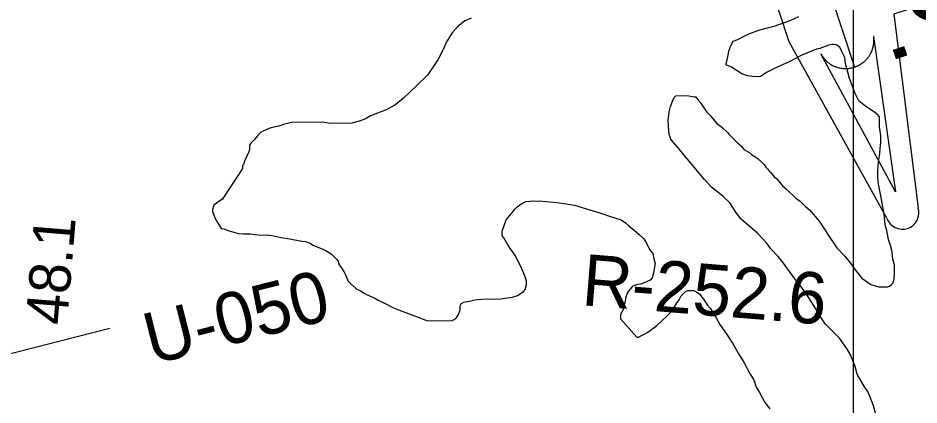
# Model space of a CAD drawing. Extents: x 3263578 to 3301413, y 764927 to 798602.
# Drawn here: x 3295210 to 3296664, y 777411 to 778036 of the extents above; entities that cross this region are included whole.
import ezdxf

# ---------------------------------------------------------------- set-up
doc = ezdxf.new("R2010")
doc.units = 0
for name, color, linetype in [('V-GRID-MAJR', 7, 'Continuous'), ('V-RIVR-RANG', 7, 'Continuous'), ('V-RIVR-RANG-IDEN', 7, 'Continuous'), ('V-SITE-VEGE', 7, 'Continuous'), ('V-TOPO-WATR-IDEN', 7, 'Continuous')]:
    doc.layers.add(name, color=color, linetype=linetype)

msp = doc.modelspace()

# ---------------------------------------------------------------- linework, layer by layer
at = {"layer": 'V-GRID-MAJR'}
msp.add_spline([(3296559.4, 775831.5), (3296556.8, 781892.5), (3296554.1, 787954.5), (3296551.5, 794016.6), (3296551.5, 794017.6)], degree=3, dxfattribs=at)
at = {"layer": 'V-RIVR-RANG'}
msp.add_line((3295358.3, 777534.4), (3294157.4, 777225.6), dxfattribs=at)
at = {"layer": 'V-SITE-VEGE'}
for p, q in [((3295930.9, 778031.6), (3295919.1, 778021.9)), ((3295941.1, 778036), (3295930.9, 778031.6)), ((3296430.5, 778023.1), (3296456, 778032.1)), ((3296456, 778032.1), (3296470.4, 778038.4)), ((3295910.7, 778012.3), (3295901.6, 777997.6)), ((3295919.1, 778021.9), (3295910.7, 778012.3)), ((3296389.6, 778010.3), (3296407.5, 778016.7)), ((3296407.5, 778016.7), (3296417.7, 778019.4)), ((3296417.7, 778019.4), (3296430.5, 778023.1)), ((3295901.6, 777997.6), (3295896.6, 777986.4)), ((3296360.8, 777992.6), (3296364.1, 777998.7)), ((3296364.1, 777998.7), (3296371.8, 778001.4)), ((3296371.8, 778001.4), (3296378.6, 778005)), ((3296378.6, 778005), (3296389.6, 778010.3)), ((3295896.6, 777986.4), (3295887.6, 777968.2)), ((3296354.4, 777968.5), (3296357.6, 777984)), ((3296357.6, 777984), (3296360.8, 777992.6)), ((3296498.9, 777985.8), (3296484.4, 777979.6)), ((3296504, 777986.8), (3296498.9, 777985.8)), ((3296518.4, 777992.2), (3296504, 777986.8)), ((3296523.6, 777993.2), (3296518.4, 777992.2)), ((3296527, 777993.2), (3296523.6, 777993.2)), ((3296530.4, 777992.4), (3296527, 777993.2)), ((3296536.5, 777989.1), (3296530.4, 777992.4)), ((3296539.2, 777983.2), (3296536.5, 777989.1)), ((3296544.5, 777972.1), (3296539.2, 777983.2)), ((3295887.6, 777968.2), (3295870.9, 777943.9)), ((3296352.8, 777962.5), (3296354.4, 777968.5)), ((3296475.1, 777976), (3296454.7, 777965.3)), ((3296484.4, 777979.6), (3296475.1, 777976)), ((3296545.6, 777962.7), (3296544.5, 777972.1)), ((3296352.9, 777959.9), (3296352.8, 777962.5)), ((3296355.5, 777959.1), (3296352.9, 777959.9)), ((3296361.5, 777956.7), (3296355.5, 777959.1)), ((3296378, 777945.8), (3296361.5, 777956.7)), ((3296430.9, 777954.6), (3296419.1, 777948.3)), ((3296440.3, 777959), (3296430.9, 777954.6)), ((3296454.7, 777965.3), (3296440.3, 777959)), ((3296549.3, 777948.3), (3296545.6, 777962.7)), ((3295870.9, 777943.9), (3295853.2, 777926.4)), ((3296387.5, 777942.6), (3296378, 777945.8)), ((3296400.3, 777941.1), (3296387.5, 777942.6)), ((3296408.1, 777941.3), (3296400.3, 777941.1)), ((3296419.1, 777948.3), (3296408.1, 777941.3)), ((3296552, 777938), (3296549.3, 777948.3)), ((3296561.1, 777914.2), (3296552, 777938)), ((3295853.2, 777926.4), (3295832.2, 777906.3)), ((3296269.1, 777907.8), (3296271.6, 777910.4)), ((3296271.6, 777910.4), (3296289.6, 777910.8)), ((3296289.6, 777910.8), (3296301.6, 777908.4)), ((3296567.3, 777902.3), (3296561.1, 777914.2)), ((3295817.9, 777894.9), (3295804.3, 777887.8)), ((3295832.2, 777906.3), (3295817.9, 777894.9)), ((3296263.3, 777893.1), (3296266.6, 777902.6)), ((3296266.6, 777902.6), (3296269.1, 777907.8)), ((3296301.6, 777908.4), (3296304.2, 777908.5)), ((3296304.2, 777908.5), (3296307.7, 777903.4)), ((3296307.7, 777903.4), (3296312.1, 777898.3)), ((3296312.1, 777898.3), (3296314.7, 777894.1)), ((3296569.9, 777899.8), (3296567.3, 777902.3)), ((3296578.6, 777893.1), (3296569.9, 777899.8)), ((3295804.3, 777887.8), (3295778.8, 777877.9)), ((3296259.5, 777870.8), (3296260.9, 777884.5)), ((3296260.9, 777884.5), (3296263.3, 777893.1)), ((3296314.7, 777894.1), (3296321.8, 777884)), ((3296321.8, 777884), (3296327.9, 777878.1)), ((3296587.3, 777887.3), (3296578.6, 777893.1)), ((3296596.8, 777880.6), (3296587.3, 777887.3)), ((3296600.3, 777876.4), (3296596.8, 777880.6)), ((3295651.3, 777866.9), (3295638.5, 777864.1)), ((3295701, 777867.8), (3295651.3, 777866.9)), ((3295711.3, 777866.3), (3295701, 777867.8)), ((3295719.9, 777865.6), (3295711.3, 777866.3)), ((3295749, 777866.2), (3295719.9, 777865.6)), ((3295762.6, 777869.9), (3295749, 777866.2)), ((3295772, 777873.5), (3295762.6, 777869.9)), ((3295778.8, 777877.9), (3295772, 777873.5)), ((3296259.7, 777861.4), (3296259.5, 777870.8)), ((3296327.9, 777878.1), (3296337.5, 777866.3)), ((3296337.5, 777866.3), (3296346.2, 777859.6)), ((3296600.6, 777860.1), (3296600.3, 777876.4)), ((3295601.9, 777851.4), (3295596.9, 777846.2)), ((3295611.3, 777855.9), (3295601.9, 777851.4)), ((3295618.1, 777858.6), (3295611.3, 777855.9)), ((3295630.9, 777861.4), (3295618.1, 777858.6)), ((3295638.5, 777864.1), (3295630.9, 777861.4)), ((3296260.8, 777847.7), (3296259.7, 777861.4)), ((3296346.2, 777859.6), (3296354.9, 777851.2)), ((3296354.9, 777851.2), (3296357.6, 777847.8)), ((3296602.6, 777845.6), (3296600.6, 777860.1)), ((3295591, 777839.2), (3295586, 777834)), ((3295596.9, 777846.2), (3295591, 777839.2)), ((3296264.4, 777839.2), (3296260.8, 777847.7)), ((3296275.8, 777825.7), (3296264.4, 777839.2)), ((3296357.6, 777847.8), (3296371.5, 777834.4)), ((3296602.8, 777835.3), (3296602.6, 777845.6)), ((3295583.6, 777822.8), (3295582, 777818.5)), ((3295586, 777834), (3295583.5, 777830.5)), ((3295583.5, 777830.5), (3295583.6, 777822.8)), ((3296284.5, 777814.7), (3296275.8, 777825.7)), ((3296371.5, 777834.4), (3296378.5, 777828.5)), ((3296378.5, 777828.5), (3296381.2, 777823.4)), ((3296381.2, 777823.4), (3296389.8, 777819.3)), ((3296600.7, 777813), (3296602.8, 777835.3)), ((3295582, 777818.5), (3295575.4, 777804.6)), ((3296299.4, 777797.9), (3296284.5, 777814.7)), ((3296389.8, 777819.3), (3296394.2, 777815.1)), ((3296394.2, 777815.1), (3296401.1, 777810.9)), ((3296401.1, 777810.9), (3296404.6, 777808.4)), ((3296404.6, 777808.4), (3296414.2, 777799.2)), ((3296599.1, 777806.1), (3296600.7, 777813)), ((3295572.2, 777792.6), (3295541.4, 777745.7)), ((3295573.8, 777799.5), (3295572.1, 777797.7)), ((3295572.1, 777797.7), (3295572.2, 777792.6)), ((3295575.4, 777804.6), (3295573.8, 777799.5)), ((3296303.8, 777792), (3296299.4, 777797.9)), ((3296414.2, 777799.2), (3296416.8, 777795)), ((3296416.8, 777795), (3296419.5, 777792.4)), ((3296597.8, 777786.4), (3296598.4, 777798.4)), ((3296598.4, 777798.4), (3296599.1, 777806.1)), ((3296317.8, 777775.1), (3296303.8, 777792)), ((3296419.5, 777792.4), (3296423, 777788.2)), ((3296423, 777788.2), (3296425.6, 777785.7)), ((3296425.6, 777785.7), (3296430, 777779.8)), ((3296430, 777779.8), (3296434.3, 777776.4)), ((3296597.9, 777777.8), (3296597.8, 777786.4)), ((3296329.2, 777762.5), (3296317.8, 777775.1)), ((3296434.3, 777776.4), (3296444, 777764.6)), ((3296444, 777764.6), (3296450.1, 777759.6)), ((3296599, 777767.6), (3296597.9, 777777.8)), ((3296602.8, 777748.8), (3296599, 777767.6)), ((3296347.5, 777748.2), (3296329.2, 777762.5)), ((3296450.1, 777759.6), (3296464.9, 777745.3)), ((3295529.6, 777736.1), (3295526.2, 777733.4)), ((3295535.5, 777740.5), (3295529.6, 777736.1)), ((3295539.8, 777743.1), (3295535.5, 777740.5)), ((3295541.4, 777745.7), (3295539.8, 777743.1)), ((3296015.4, 777730.8), (3296023, 777736.1)), ((3296023, 777736.1), (3296029.8, 777739.6)), ((3296029.8, 777739.6), (3296042.7, 777740.7)), ((3296042.7, 777740.7), (3296057.2, 777740.1)), ((3296057.2, 777740.1), (3296079.5, 777738)), ((3296079.5, 777738), (3296094.2, 777735.7)), ((3296094.2, 777735.7), (3296107.9, 777733.4)), ((3296358.8, 777737.3), (3296347.5, 777748.2)), ((3296369.4, 777720.4), (3296358.8, 777737.3)), ((3296464.9, 777745.3), (3296472.7, 777739.5)), ((3296472.7, 777739.5), (3296480.6, 777731.9)), ((3296604.7, 777736.9), (3296602.8, 777748.8)), ((3296607.5, 777722.4), (3296604.7, 777736.9)), ((3295526.2, 777733.4), (3295523.8, 777726.5)), ((3295523.8, 777726.5), (3295523.9, 777722.3)), ((3295523.9, 777722.3), (3295525.6, 777719.7)), ((3295997.8, 777709.9), (3296008.7, 777722.9)), ((3296008.7, 777722.9), (3296012.1, 777727.3)), ((3296012.1, 777727.3), (3296015.4, 777730.8)), ((3296107.9, 777733.4), (3296127.7, 777727.8)), ((3296127.7, 777727.8), (3296149.3, 777721.3)), ((3296149.3, 777721.3), (3296164.8, 777715.6)), ((3296377.3, 777711.1), (3296369.4, 777720.4)), ((3296480.6, 777731.9), (3296487.5, 777726.1)), ((3296487.5, 777726.1), (3296503.3, 777707.5)), ((3296608.6, 777713.8), (3296607.5, 777722.4)), ((3295525.6, 777719.7), (3295527.5, 777712.9)), ((3295527.5, 777712.9), (3295531.9, 777705.3)), ((3295991.3, 777691.8), (3295997.8, 777709.9)), ((3296164.8, 777715.6), (3296183.7, 777710)), ((3296183.7, 777710), (3296190.7, 777705)), ((3296393, 777697.7), (3296377.3, 777711.1)), ((3296503.3, 777707.5), (3296513, 777693.1)), ((3296609.6, 777701.8), (3296608.6, 777713.8)), ((3295531.9, 777705.3), (3295534.6, 777701.1)), ((3295534.6, 777701.1), (3295538.1, 777696)), ((3295538.1, 777696), (3295542.4, 777695.2)), ((3295542.4, 777695.2), (3295551, 777691.9)), ((3295551, 777691.9), (3295565.7, 777687.9)), ((3295991.5, 777684.1), (3295991.3, 777691.8)), ((3296190.7, 777705), (3296195.9, 777699.9)), ((3296195.9, 777699.9), (3296204.6, 777693.3)), ((3296204.6, 777693.3), (3296213.3, 777685.7)), ((3296403.4, 777688.5), (3296393, 777697.7)), ((3296513, 777693.1), (3296515.7, 777688)), ((3296612.4, 777692.5), (3296609.6, 777701.8)), ((3296615.2, 777678), (3296612.4, 777692.5)), ((3295565.7, 777687.9), (3295573.4, 777687.2)), ((3295573.4, 777687.2), (3295585.4, 777687.5)), ((3295585.4, 777687.5), (3295592.3, 777685.9)), ((3295592.3, 777685.9), (3295602.5, 777685.2)), ((3295602.5, 777685.2), (3295612, 777685.4)), ((3295612, 777685.4), (3295619.7, 777684.7)), ((3295619.7, 777684.7), (3295630, 777682.3)), ((3295630, 777682.3), (3295637.8, 777680.7)), ((3295637.8, 777680.7), (3295648.9, 777679.2)), ((3295648.9, 777679.2), (3295667.8, 777675.3)), ((3295994.1, 777680.7), (3295991.5, 777684.1)), ((3295998.5, 777673.1), (3295994.1, 777680.7)), ((3296213.3, 777685.7), (3296220.3, 777679)), ((3296220.3, 777679), (3296223.8, 777673.1)), ((3296418.3, 777672.5), (3296403.4, 777688.5)), ((3296515.7, 777688), (3296531.5, 777664.4)), ((3296618, 777668.6), (3296615.2, 777678)), ((3295667.8, 777675.3), (3295673.8, 777674.6)), ((3295673.8, 777674.6), (3295681.6, 777672.2)), ((3295681.6, 777672.2), (3295686, 777668.8)), ((3295686, 777668.8), (3295698, 777663.9)), ((3295698, 777663.9), (3295705.8, 777660.6)), ((3296003.8, 777664.6), (3295998.5, 777673.1)), ((3296012.7, 777651.9), (3296003.8, 777664.6)), ((3296223.8, 777673.1), (3296229.2, 777662)), ((3296229.2, 777662), (3296234.5, 777655.3)), ((3296425.3, 777663.2), (3296418.3, 777672.5)), ((3296436.7, 777650.6), (3296425.3, 777663.2)), ((3296531.5, 777664.4), (3296544.6, 777650.9)), ((3296620.8, 777658.4), (3296618, 777668.6)), ((3295705.8, 777660.6), (3295715.3, 777654.8)), ((3295715.3, 777654.8), (3295724.1, 777646.4)), ((3296022.5, 777631.5), (3296012.7, 777651.9)), ((3296234.5, 777655.3), (3296236.3, 777646.7)), ((3296445.5, 777639.6), (3296436.7, 777650.6)), ((3296544.6, 777650.9), (3296551.7, 777642.5)), ((3296621.8, 777646.4), (3296620.8, 777658.4)), ((3295724.1, 777646.4), (3295726.7, 777643)), ((3295726.7, 777643), (3295727.7, 777637.9)), ((3295727.7, 777637.9), (3295730.3, 777634.5)), ((3295730.3, 777634.5), (3295735.6, 777626.1)), ((3296236.3, 777646.7), (3296238.2, 777639.1)), ((3296238.2, 777639.1), (3296236.6, 777630.5)), ((3296462.2, 777616.8), (3296445.5, 777639.6)), ((3296551.7, 777642.5), (3296563.1, 777626.4)), ((3296624.6, 777637), (3296621.8, 777646.4)), ((3296624.8, 777623.3), (3296624.6, 777637)), ((3295735.6, 777626.1), (3295739.1, 777620.1)), ((3295739.1, 777620.1), (3295742.7, 777610.8)), ((3296027.8, 777619.6), (3296022.5, 777631.5)), ((3296028.8, 777616.2), (3296027.8, 777619.6)), ((3296235.9, 777623.6), (3296233.5, 777615.9)), ((3296236.6, 777630.5), (3296235.9, 777623.6)), ((3296563.1, 777626.4), (3296571.9, 777615.4)), ((3296624.2, 777613.9), (3296624.8, 777623.3)), ((3295742.7, 777610.8), (3295755.8, 777598.2)), ((3296028.3, 777597.4), (3296030.7, 777605.1)), ((3296030.6, 777611.1), (3296028.8, 777616.2)), ((3296030.7, 777605.1), (3296030.6, 777611.1)), ((3296209.7, 777605.1), (3296202.1, 777602.4)), ((3296214.8, 777606.1), (3296209.7, 777605.1)), ((3296221.6, 777608.8), (3296214.8, 777606.1)), ((3296224.2, 777609.7), (3296221.6, 777608.8)), ((3296230.1, 777612.4), (3296224.2, 777609.7)), ((3296233.5, 777615.9), (3296230.1, 777612.4)), ((3296476.2, 777599.1), (3296462.2, 777616.8)), ((3296571.9, 777615.4), (3296586.6, 777605.5)), ((3296586.6, 777605.5), (3296599.6, 777601.4)), ((3296616.7, 777602.6), (3296620, 777605.2)), ((3296620, 777605.2), (3296622.6, 777607.8)), ((3296622.6, 777607.8), (3296624.2, 777613.9)), ((3295755.8, 777598.2), (3295762.7, 777594.9)), ((3295762.7, 777594.9), (3295768.8, 777591.6)), ((3295768.8, 777591.6), (3295772.3, 777589.1)), ((3295772.3, 777589.1), (3295786.1, 777583.3)), ((3296016.4, 777587.7), (3296020.7, 777590.4)), ((3296020.7, 777590.4), (3296025.8, 777593.9)), ((3296025.8, 777593.9), (3296028.3, 777597.4)), ((3296192.9, 777591.1), (3296190.4, 777583.3)), ((3296195.4, 777594.6), (3296192.9, 777591.1)), ((3296200.4, 777600.7), (3296195.4, 777594.6)), ((3296202.1, 777602.4), (3296200.4, 777600.7)), ((3296280.3, 777586.8), (3296287, 777593.7)), ((3296287, 777593.7), (3296291.3, 777595.5)), ((3296291.3, 777595.5), (3296300.7, 777595.7)), ((3296300.7, 777595.7), (3296306.8, 777592.4)), ((3296306.8, 777592.4), (3296310.2, 777589.9)), ((3296310.2, 777589.9), (3296313.8, 777584.8)), ((3296485.1, 777585.5), (3296476.2, 777599.1)), ((3296599.6, 777601.4), (3296613.3, 777601.7)), ((3296613.3, 777601.7), (3296616.7, 777602.6)), ((3295786.1, 777583.3), (3295791.3, 777580)), ((3295791.3, 777580), (3295797.3, 777577.6)), ((3295797.3, 777577.6), (3295803.4, 777574.3)), ((3295924.2, 777572.3), (3295925.9, 777574.9)), ((3295925.9, 777574.9), (3295929.3, 777576.7)), ((3295929.3, 777576.7), (3295931.8, 777577.6)), ((3295931.8, 777577.6), (3295938.7, 777578.5)), ((3295938.7, 777578.5), (3295947.2, 777580.4)), ((3295947.2, 777580.4), (3295958.3, 777581.5)), ((3295958.3, 777581.5), (3295989.1, 777582.1)), ((3295989.1, 777582.1), (3296000.2, 777584)), ((3296000.2, 777584), (3296007.9, 777585)), ((3296007.9, 777585), (3296016.4, 777587.7)), ((3296189.7, 777577.3), (3296187.2, 777570.4)), ((3296190.4, 777583.3), (3296189.7, 777577.3)), ((3296265.4, 777562.5), (3296272.8, 777574.6)), ((3296272.8, 777574.6), (3296277, 777580.7)), ((3296277, 777580.7), (3296280.3, 777586.8)), ((3296313.8, 777584.8), (3296316.4, 777581.5)), ((3296316.4, 777581.5), (3296322.6, 777572.1)), ((3296494.8, 777570.3), (3296485.1, 777585.5)), ((3295803.4, 777574.3), (3295812.9, 777569.3)), ((3295812.9, 777569.3), (3295819.8, 777566)), ((3295819.8, 777566), (3295854.3, 777552.9)), ((3295921.1, 777556.8), (3295923.5, 777564.5)), ((3295923.4, 777568.8), (3295924.2, 777572.3)), ((3295923.5, 777564.5), (3295923.4, 777568.8)), ((3296186.5, 777565.3), (3296182.4, 777556.6)), ((3296187.2, 777570.4), (3296186.5, 777565.3)), ((3296257.8, 777554.6), (3296265.4, 777562.5)), ((3296322.6, 777572.1), (3296326.9, 777567.1)), ((3296326.9, 777567.1), (3296337.5, 777550.2)), ((3296500.1, 777561.8), (3296494.8, 777570.3)), ((3296507.2, 777550), (3296500.1, 777561.8)), ((3295854.3, 777552.9), (3295862.1, 777549.7)), ((3295862.1, 777549.7), (3295869.9, 777547.2)), ((3295869.9, 777547.2), (3295875, 777546.5)), ((3295875, 777546.5), (3295910.1, 777547.2)), ((3295910.1, 777547.2), (3295912.7, 777548.1)), ((3295912.7, 777548.1), (3295917.8, 777551.6)), ((3295917.8, 777551.6), (3295921.1, 777556.8)), ((3296182.4, 777556.6), (3296182.5, 777549.8)), ((3296182.5, 777549.8), (3296208.8, 777520.3)), ((3296241, 777538.9), (3296248.5, 777545.9)), ((3296248.5, 777545.9), (3296257.8, 777554.6)), ((3296337.5, 777550.2), (3296342.9, 777540.8)), ((3296513.3, 777541.5), (3296507.2, 777550)), ((3296226.6, 777528.3), (3296241, 777538.9)), ((3296342.9, 777540.8), (3296355.2, 777523.1)), ((3296526.4, 777528.1), (3296513.3, 777541.5)), ((3296208.8, 777520.3), (3296211.3, 777520.3)), ((3296211.3, 777520.3), (3296226.6, 777528.3)), ((3296355.2, 777523.1), (3296363.1, 777510.4)), ((3296536, 777518.8), (3296526.4, 777528.1)), ((3296547.5, 777501.9), (3296536, 777518.8)), ((3296363.1, 777510.4), (3296373.8, 777491.7)), ((3296553.7, 777491.7), (3296547.5, 777501.9)), ((3296373.8, 777491.7), (3296381.7, 777479.9)), ((3296560.9, 777473), (3296553.7, 777491.7)), ((3296381.7, 777479.9), (3296391.5, 777460.4)), ((3296564.6, 777460.3), (3296560.9, 777473)), ((3296391.5, 777460.4), (3296397.7, 777451.1)), ((3296576.1, 777439.9), (3296564.6, 777460.3)), ((3296397.7, 777451.1), (3296401.3, 777439.2)), ((3296401.3, 777439.2), (3296406.6, 777430.7)), ((3296406.6, 777430.7), (3296415.5, 777414.6)), ((3296581.4, 777432.3), (3296576.1, 777439.9)), ((3296590.3, 777411.1), (3296581.4, 777432.3)), ((3296415.5, 777414.6), (3296423.4, 777404.5)), ((3296594, 777397.4), (3296590.3, 777411.1))]:
    msp.add_line(p, q, dxfattribs=at)
at = {"layer": 'V-TOPO-WATR-IDEN'}
msp.add_line((3296324.9, 778670.1), (3296560, 777956.6), dxfattribs=at)
for points in [[(3296272.5, 778913.9), (3296423.8, 778648.6), (3296561.3, 778693.9), (3296761.1, 778087.4), (3296623.7, 778042.1), (3296662.8, 777729.4)], [(3296612.5, 777712.8), (3296454.7, 777997.6), (3296391, 778190.8), (3296243.5, 778142.2), (3296184.3, 778321.8), (3296331.9, 778370.4), (3296261.5, 778583.9), (3296222.1, 778897.3)]]:
    msp.add_lwpolyline(points, dxfattribs=at)
msp.add_lwpolyline([(3296591, 778006.3), (3296626.5, 777754.9), (3296505.6, 777978.2), (3296507.9, 777974.3), (3296510.6, 777970.8), (3296511.8, 777969.4), (3296512.8, 777968.3), (3296514.2, 777967), (3296515.5, 777965.7), (3296516.7, 777964.7), (3296518.4, 777963.4), (3296520.4, 777962), (3296521.4, 777961.3), (3296522.9, 777960.5), (3296524.8, 777959.4), (3296526.4, 777958.6), (3296528.1, 777957.9), (3296529.2, 777957.4), (3296530.5, 777957), (3296532, 777956.5), (3296533.5, 777956), (3296534.9, 777955.6), (3296536.1, 777955.4), (3296537.9, 777955), (3296539.7, 777954.8), (3296541, 777954.6), (3296542.7, 777954.5), (3296544.1, 777954.4), (3296545.4, 777954.4), (3296546.4, 777954.4), (3296547.9, 777954.4), (3296549.4, 777954.5), (3296550.9, 777954.6), (3296552.4, 777954.8), (3296553.7, 777955.1), (3296555.2, 777955.3), (3296556.4, 777955.6), (3296558.1, 777956.1), (3296560, 777956.6), (3296560.6, 777956.9), (3296561.5, 777957.2), (3296562.5, 777957.6), (3296563.5, 777958), (3296564.5, 777958.4), (3296565.4, 777958.8), (3296566.5, 777959.3), (3296567.2, 777959.7), (3296568.3, 777960.3), (3296569.2, 777960.9), (3296569.9, 777961.3), (3296571.6, 777962.4), (3296572.5, 777963), (3296573.1, 777963.4), (3296574, 777964.2), (3296574.9, 777964.9), (3296575.8, 777965.6), (3296576.8, 777966.5), (3296577.7, 777967.4), (3296578.4, 777968.1), (3296579, 777968.7), (3296579.7, 777969.5), (3296580.4, 777970.3), (3296581.2, 777971.2), (3296581.9, 777972.1), (3296582.7, 777973.1), (3296583.6, 777974.4), (3296584.2, 777975.3), (3296584.8, 777976.4), (3296585.4, 777977.4), (3296585.9, 777978.2), (3296586.4, 777979.2), (3296587.1, 777980.6), (3296587.1, 777980.6), (3296587.5, 777981.5), (3296587.8, 777982.1), (3296588.2, 777983.1), (3296588.6, 777984.3), (3296589, 777985.2), (3296589.3, 777986.1), (3296589.6, 777987.2), (3296589.9, 777988.3), (3296590.1, 777989.1), (3296590.4, 777990.2), (3296590.7, 777991.6), (3296590.8, 777992.4), (3296590.9, 777993.1), (3296591, 777993.7), (3296591.1, 777994.5), (3296591.2, 777995.5), (3296591.3, 777996.4), (3296591.4, 777997.4), (3296591.4, 777998.4), (3296591.5, 777999.6), (3296591.5, 778000.4), (3296591.4, 778001.5), (3296591.4, 778002.9), (3296591.3, 778004), (3296591.2, 778004.7), (3296591.1, 778005.5), (3296591.1, 778006)], close=True, dxfattribs=at)
msp.add_arc((3296637.6, 777721.1), 26.5, 198.2394, 18.2394, dxfattribs=at)

# ---------------------------------------------------------------- texts
at = {"layer": 'V-RIVR-RANG'}
msp.add_text('48.1', height=67, rotation=85.2583, dxfattribs=at).set_placement((3295288.8, 777538.6))
at = {"layer": 'V-RIVR-RANG-IDEN'}
for s, rotation, p in [('R-252.6', 355.3999, (3296118.3, 777572)), ('U-050', 14.2813, (3295425.7, 777475.4))]:
    msp.add_text(s, height=83, rotation=rotation, dxfattribs=at).set_placement(p)
at = {"layer": 'V-TOPO-WATR-IDEN'}
msp.add_text('L.W.R.P.', height=124.5, rotation=288.2393, dxfattribs=at).set_placement((3296423.2, 778587.6))

doc.saveas('drawing.dxf')
